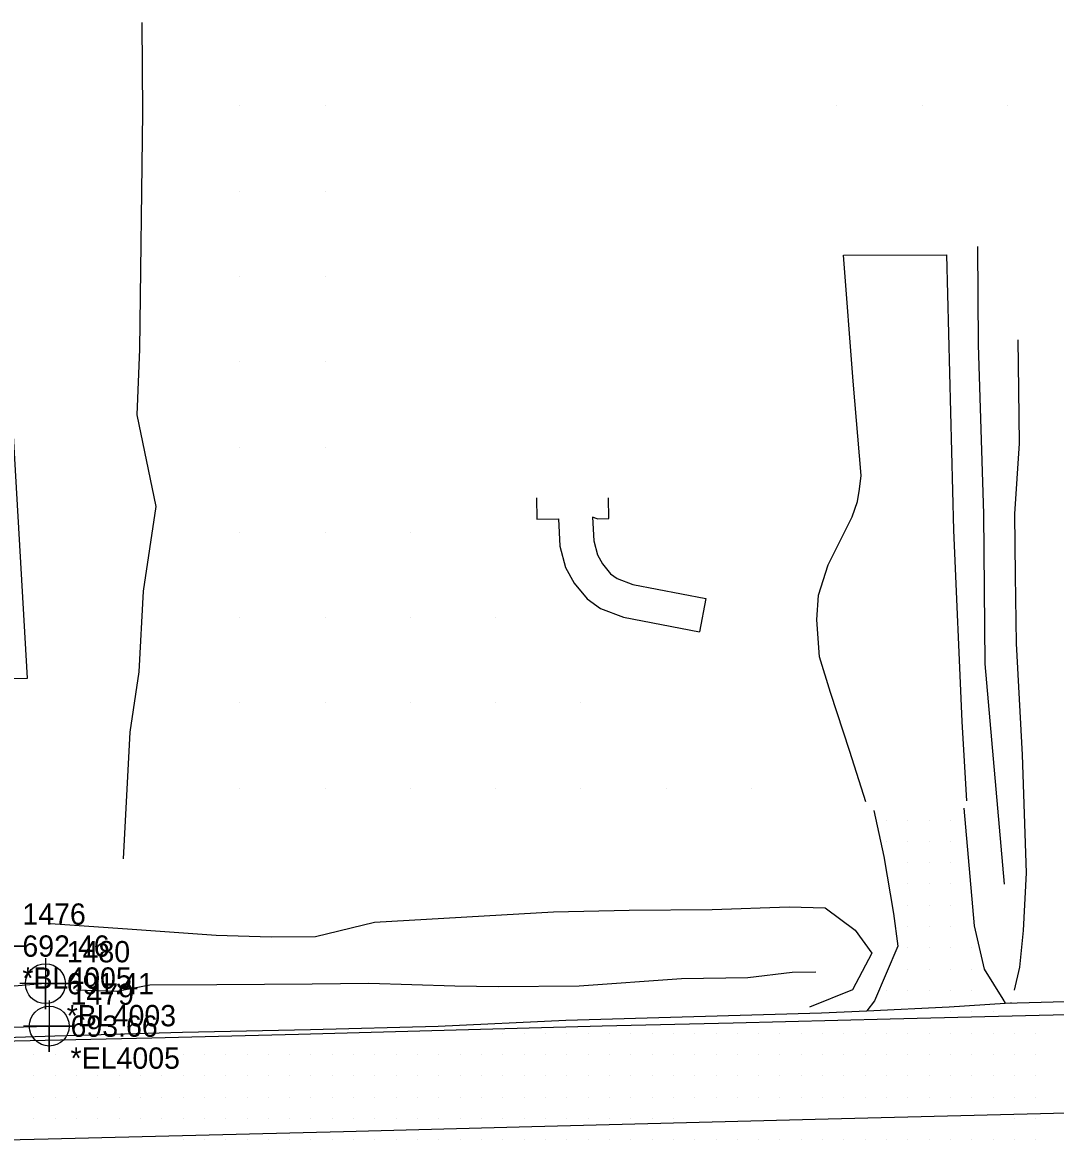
# Model space of a CAD drawing. Extents: x 1755643 to 1760494, y 736519 to 737621.
# Drawn here: x 1758089.9 to 1758211.1, y 736993.2 to 737124.8 of the extents above; entities that cross this region are included whole.
import ezdxf

# ---------------------------------------------------------------- set-up
doc = ezdxf.new("R2010")
doc.units = 0
for name, color, linetype in [('Exist Horizontal Alignment Direction Label', 7, 'Continuous'), ('Exist Railroads Standard Gauge', 7, 'Continuous'), ('Old_Level_1', 7, 'Continuous'), ('Old_Level_10', 7, 'Continuous'), ('Old_Level_2', 7, 'Continuous'), ('Old_Level_3', 7, 'Continuous'), ('Prop Corridor Linear Feature', 7, 'Continuous'), ('Prop Dimension', 7, 'Continuous'), ('Prop EOT Dash', 7, 'Continuous'), ('Prop Horizontal Alignment Direction Label', 7, 'Continuous'), ('Prop Lane Lines', 7, 'Continuous'), ('Prop Paint Stripe', 7, 'Continuous'), ('Scratch_Level_1', 7, 'Continuous'), ('Scratch_Level_2', 7, 'Continuous'), ('Scratch_Level_5', 7, 'Continuous'), ('Scratch_Level_6', 7, 'Continuous'), ('Scratch_Level_9', 7, 'Continuous')]:
    doc.layers.add(name, color=color, linetype=linetype)

msp = doc.modelspace()

# ---------------------------------------------------------------- linework, layer by layer
at = {"layer": 'Exist Railroads Standard Gauge'}
for p, q in [((1758157.31, 737066.59), (1758156.76, 737066.79)), ((1758170.05, 737057.25), (1758169.3, 737053.32))]:
    msp.add_line(p, q, dxfattribs=at)
for points in [[(1758103.92, 737124.79), (1758104, 737114.24), (1758103.64, 737086.47), (1758103.34, 737078.79), (1758105.56, 737068.02), (1758104.08, 737058.08), (1758103.56, 737048.62), (1758102.52, 737041.54), (1758101.73, 737026.7)], [(1758205.08, 737023.71), (1758202.81, 737049.55), (1758202.67, 737067.16), (1758202.04, 737086.99), (1758201.95, 737098.53)], [(1758188.82, 737033.39), (1758186.96, 737039.27), (1758184.66, 737046.19), (1758183.38, 737050.38), (1758183.08, 737054.72), (1758183.28, 737057.62), (1758184.41, 737061.19), (1758187.21, 737066.82), (1758187.83, 737068.59), (1758188.06, 737070.05), (1758188.29, 737071.64), (1758187.35, 737082.71), (1758186.21, 737097.48), (1758198.28, 737097.55), (1758199.09, 737065.26), (1758200.07, 737042.8), (1758200.61, 737033.5)], [(1758206.24, 737011.31), (1758206.89, 737013.98), (1758207.3, 737018.28), (1758207.67, 737025.04), (1758207.21, 737038.89), (1758206.48, 737051.96), (1758206.38, 737059.92), (1758206.31, 737067.16), (1758206.84, 737075.4), (1758206.78, 737081.71), (1758206.7, 737087.55)], [(1758061.63, 737030.06), (1758062.06, 737032.81), (1758064.05, 737038.81), (1758066.35, 737043.44), (1758068.93, 737046.42), (1758071.04, 737047.5), (1758090.51, 737047.87), (1758088.31, 737085.8)], [(1758150.21, 737069.02), (1758150.23, 737066.54), (1758152.76, 737066.56)], [(1758157.31, 737066.59), (1758158.67, 737066.6), (1758158.65, 737069.02)], [(1758152.76, 737066.56), (1758152.95, 737063.36), (1758153.6, 737060.86), (1758154.61, 737059.04), (1758156.13, 737057.2), (1758157.72, 737056.04), (1758160.39, 737055.03), (1758169.3, 737053.32)], [(1758156.76, 737066.79), (1758156.92, 737063.99), (1758157.35, 737062.36), (1758157.94, 737061.3), (1758158.89, 737060.13), (1758159.64, 737059.59), (1758161.48, 737058.89), (1758170.05, 737057.25)], [(1758093.18, 737019.13), (1758102.78, 737018.47), (1758112.61, 737017.75), (1758119.07, 737017.54), (1758124.28, 737017.58), (1758131.2, 737019.28), (1758152.21, 737020.47), (1758161.05, 737020.66), (1758170.8, 737020.74), (1758179.84, 737021.06), (1758184.07, 737020.96), (1758187.57, 737018.35), (1758189.52, 737015.64), (1758187.25, 737011.33), (1758182.21, 737009.29)], [(1758096.23, 737011.32), (1758100.97, 737011.19), (1758104.85, 737011.94), (1758112.72, 737011.97), (1758123.9, 737012.05), (1758130.53, 737012.1), (1758140.62, 737011.79), (1758145.72, 737011.71), (1758155.21, 737011.79), (1758167.21, 737012.66), (1758174.99, 737012.78), (1758180.19, 737013.39), (1758182.97, 737013.44)], [(1758205.87, 737009.83), (1758205.88, 737009.85)]]:
    msp.add_lwpolyline(points, dxfattribs=at)
at = {"layer": 'Old_Level_10'}
msp.add_lwpolyline([(1758092.6, 737015.06), (1758092.6, 737009.06), (1758092.6, 737012.06), (1758095.6, 737012.06), (1758089.6, 737012.06)], dxfattribs=at)
msp.add_circle((1758092.6, 737012.06), 2.34, dxfattribs=at)
at = {"layer": 'Prop Corridor Linear Feature'}
for points in [[(1758188.93, 737008.88), (1758198.61, 737009.34), (1758205.15, 737009.77)], [(1758205.15, 737009.77), (1758213.6, 737010), (1758228.6, 737009.79)]]:
    msp.add_lwpolyline(points, dxfattribs=at)
at = {"layer": 'Prop Dimension'}
msp.add_lwpolyline([(1758092.6, 737012.06), (1758073.32, 737010.44), (1758071.36, 737012.75)], dxfattribs=at)
at = {"layer": 'Prop Lane Lines'}
for points in [[(1758087.4, 737019.47), (1758087.4, 737013.47), (1758087.4, 737016.47), (1758090.4, 737016.47), (1758084.4, 737016.47)], [(1758093.05, 737010.08), (1758093.05, 737004.08), (1758093.05, 737007.08), (1758096.05, 737007.08), (1758090.05, 737007.08)]]:
    msp.add_lwpolyline(points, dxfattribs=at)
msp.add_circle((1758093.05, 737007.08), 2.34, dxfattribs=at)
at = {"layer": 'Prop Paint Stripe'}
for p, q in [((1758115.41, 737115), (1758115.41, 737115)), ((1758125.41, 737115), (1758125.41, 737115)), ((1758185.41, 737115), (1758185.41, 737115)), ((1758195.42, 737115), (1758195.42, 737115)), ((1758205.42, 737115), (1758205.42, 737115)), ((1758115.41, 737105), (1758115.41, 737105)), ((1758125.41, 737105), (1758125.41, 737105)), ((1758115.41, 737094.99), (1758115.41, 737094.99)), ((1758125.41, 737094.99), (1758125.41, 737094.99)), ((1758115.41, 737084.99), (1758115.41, 737084.99)), ((1758125.41, 737084.99), (1758125.41, 737084.99)), ((1758115.41, 737074.99), (1758115.41, 737074.99)), ((1758125.41, 737074.99), (1758125.41, 737074.99)), ((1758115.41, 737064.99), (1758115.41, 737064.99)), ((1758125.41, 737064.99), (1758125.41, 737064.99)), ((1758135.41, 737064.99), (1758135.41, 737064.99)), ((1758115.41, 737054.99), (1758115.41, 737054.99)), ((1758125.41, 737054.99), (1758125.41, 737054.99)), ((1758135.41, 737054.99), (1758135.41, 737054.99)), ((1758145.41, 737054.99), (1758145.41, 737054.99)), ((1758115.41, 737044.99), (1758115.41, 737044.99)), ((1758125.41, 737044.99), (1758125.41, 737044.99)), ((1758135.41, 737044.99), (1758135.41, 737044.99)), ((1758145.41, 737044.99), (1758145.41, 737044.99)), ((1758155.41, 737044.99), (1758155.41, 737044.99)), ((1758115.41, 737034.99), (1758115.41, 737034.99)), ((1758125.41, 737034.99), (1758125.41, 737034.99)), ((1758135.41, 737034.99), (1758135.41, 737034.99)), ((1758145.41, 737034.99), (1758145.41, 737034.99)), ((1758155.41, 737034.99), (1758155.41, 737034.99)), ((1758165.41, 737034.99), (1758165.41, 737034.99)), ((1758175.41, 737034.99), (1758175.41, 737034.99))]:
    msp.add_line(p, q, dxfattribs=at)
at = {"layer": 'Scratch_Level_1'}
msp.add_lwpolyline([(1758064.64, 737006.23), (1758067.75, 737005.95), (1758070.73, 737005.31), (1758078.73, 737005.43), (1758093.71, 737005.95), (1758108.69, 737006.38), (1758123.68, 737006.69), (1758138.67, 737007.07), (1758153.65, 737007.78), (1758168.64, 737008.2), (1758183.63, 737008.63), (1758188.93, 737008.88)], dxfattribs=at)
at = {"layer": 'Scratch_Level_2'}
for p, q in [((1758191.25, 737031.25), (1758191.25, 737031.25)), ((1758193.75, 737031.25), (1758193.75, 737031.25)), ((1758196.25, 737031.25), (1758196.25, 737031.25)), ((1758198.75, 737031.25), (1758198.75, 737031.25)), ((1758191.25, 737028.75), (1758191.25, 737028.75)), ((1758193.75, 737028.75), (1758193.75, 737028.75)), ((1758196.25, 737028.75), (1758196.25, 737028.75)), ((1758198.75, 737028.75), (1758198.75, 737028.75)), ((1758193.75, 737026.25), (1758193.75, 737026.25)), ((1758196.25, 737026.25), (1758196.25, 737026.25)), ((1758198.75, 737026.25), (1758198.75, 737026.25)), ((1758193.75, 737023.75), (1758193.75, 737023.75)), ((1758196.25, 737023.75), (1758196.25, 737023.75)), ((1758198.75, 737023.75), (1758198.75, 737023.75)), ((1758193.75, 737021.25), (1758193.75, 737021.25)), ((1758196.25, 737021.25), (1758196.25, 737021.25)), ((1758198.75, 737021.25), (1758198.75, 737021.25)), ((1758193.75, 737018.75), (1758193.75, 737018.75)), ((1758196.25, 737018.75), (1758196.25, 737018.75)), ((1758198.75, 737018.75), (1758198.75, 737018.75)), ((1758193.75, 737016.25), (1758193.75, 737016.25)), ((1758196.25, 737016.25), (1758196.25, 737016.25)), ((1758198.75, 737016.25), (1758198.75, 737016.25)), ((1758201.25, 737016.25), (1758201.25, 737016.25)), ((1758193.75, 737013.75), (1758193.75, 737013.75)), ((1758196.25, 737013.75), (1758196.25, 737013.75)), ((1758198.75, 737013.75), (1758198.75, 737013.75)), ((1758201.25, 737013.75), (1758201.25, 737013.75)), ((1758191.25, 737011.25), (1758191.25, 737011.25)), ((1758193.75, 737011.25), (1758193.75, 737011.25)), ((1758196.25, 737011.25), (1758196.25, 737011.25)), ((1758198.75, 737011.25), (1758198.75, 737011.25)), ((1758201.25, 737011.25), (1758201.25, 737011.25)), ((1758198.75, 737008.75), (1758198.75, 737008.75)), ((1758201.25, 737008.75), (1758201.25, 737008.75)), ((1758203.75, 737008.75), (1758203.75, 737008.75)), ((1758146.25, 737006.25), (1758146.25, 737006.25)), ((1758148.75, 737006.25), (1758148.75, 737006.25)), ((1758151.25, 737006.25), (1758151.25, 737006.25)), ((1758153.75, 737006.25), (1758153.75, 737006.25)), ((1758156.25, 737006.25), (1758156.25, 737006.25)), ((1758158.75, 737006.25), (1758158.75, 737006.25)), ((1758161.25, 737006.25), (1758161.25, 737006.25)), ((1758163.75, 737006.25), (1758163.75, 737006.25)), ((1758166.25, 737006.25), (1758166.25, 737006.25)), ((1758168.75, 737006.25), (1758168.75, 737006.25)), ((1758171.25, 737006.25), (1758171.25, 737006.25)), ((1758173.75, 737006.25), (1758173.75, 737006.25)), ((1758176.25, 737006.25), (1758176.25, 737006.25)), ((1758178.75, 737006.25), (1758178.75, 737006.25)), ((1758181.25, 737006.25), (1758181.25, 737006.25)), ((1758183.75, 737006.25), (1758183.75, 737006.25)), ((1758186.25, 737006.25), (1758186.25, 737006.25)), ((1758188.75, 737006.25), (1758188.75, 737006.25)), ((1758191.25, 737006.25), (1758191.25, 737006.25)), ((1758193.75, 737006.25), (1758193.75, 737006.25)), ((1758196.25, 737006.25), (1758196.25, 737006.25)), ((1758198.75, 737006.25), (1758198.75, 737006.25)), ((1758201.25, 737006.25), (1758201.25, 737006.25)), ((1758203.75, 737006.25), (1758203.75, 737006.25)), ((1758206.25, 737006.25), (1758206.25, 737006.25)), ((1758208.75, 737006.25), (1758208.75, 737006.25)), ((1758091.25, 737003.75), (1758091.25, 737003.75)), ((1758093.75, 737003.75), (1758093.75, 737003.75)), ((1758096.25, 737003.75), (1758096.25, 737003.75)), ((1758098.75, 737003.75), (1758098.75, 737003.75)), ((1758101.25, 737003.75), (1758101.25, 737003.75)), ((1758103.75, 737003.75), (1758103.75, 737003.75)), ((1758106.25, 737003.75), (1758106.25, 737003.75)), ((1758108.75, 737003.75), (1758108.75, 737003.75)), ((1758111.25, 737003.75), (1758111.25, 737003.75)), ((1758113.75, 737003.75), (1758113.75, 737003.75)), ((1758116.25, 737003.75), (1758116.25, 737003.75)), ((1758118.75, 737003.75), (1758118.75, 737003.75)), ((1758121.25, 737003.75), (1758121.25, 737003.75)), ((1758123.75, 737003.75), (1758123.75, 737003.75)), ((1758126.25, 737003.75), (1758126.25, 737003.75)), ((1758128.75, 737003.75), (1758128.75, 737003.75)), ((1758131.25, 737003.75), (1758131.25, 737003.75)), ((1758133.75, 737003.75), (1758133.75, 737003.75)), ((1758136.25, 737003.75), (1758136.25, 737003.75)), ((1758138.75, 737003.75), (1758138.75, 737003.75)), ((1758141.25, 737003.75), (1758141.25, 737003.75)), ((1758143.75, 737003.75), (1758143.75, 737003.75)), ((1758146.25, 737003.75), (1758146.25, 737003.75)), ((1758148.75, 737003.75), (1758148.75, 737003.75)), ((1758151.25, 737003.75), (1758151.25, 737003.75)), ((1758153.75, 737003.75), (1758153.75, 737003.75)), ((1758156.25, 737003.75), (1758156.25, 737003.75)), ((1758158.75, 737003.75), (1758158.75, 737003.75)), ((1758161.25, 737003.75), (1758161.25, 737003.75)), ((1758163.75, 737003.75), (1758163.75, 737003.75)), ((1758166.25, 737003.75), (1758166.25, 737003.75)), ((1758168.75, 737003.75), (1758168.75, 737003.75)), ((1758171.25, 737003.75), (1758171.25, 737003.75)), ((1758173.75, 737003.75), (1758173.75, 737003.75)), ((1758176.25, 737003.75), (1758176.25, 737003.75)), ((1758178.75, 737003.75), (1758178.75, 737003.75)), ((1758181.25, 737003.75), (1758181.25, 737003.75)), ((1758183.75, 737003.75), (1758183.75, 737003.75)), ((1758186.25, 737003.75), (1758186.25, 737003.75)), ((1758188.75, 737003.75), (1758188.75, 737003.75)), ((1758191.25, 737003.75), (1758191.25, 737003.75)), ((1758193.75, 737003.75), (1758193.75, 737003.75)), ((1758196.25, 737003.75), (1758196.25, 737003.75)), ((1758198.75, 737003.75), (1758198.75, 737003.75)), ((1758201.25, 737003.75), (1758201.25, 737003.75)), ((1758203.75, 737003.75), (1758203.75, 737003.75)), ((1758206.25, 737003.75), (1758206.25, 737003.75)), ((1758208.75, 737003.75), (1758208.75, 737003.75)), ((1758091.25, 737001.25), (1758091.25, 737001.25)), ((1758093.75, 737001.25), (1758093.75, 737001.25)), ((1758096.25, 737001.25), (1758096.25, 737001.25)), ((1758098.75, 737001.25), (1758098.75, 737001.25)), ((1758101.25, 737001.25), (1758101.25, 737001.25)), ((1758103.75, 737001.25), (1758103.75, 737001.25)), ((1758106.25, 737001.25), (1758106.25, 737001.25)), ((1758108.75, 737001.25), (1758108.75, 737001.25)), ((1758111.25, 737001.25), (1758111.25, 737001.25)), ((1758113.75, 737001.25), (1758113.75, 737001.25)), ((1758116.25, 737001.25), (1758116.25, 737001.25)), ((1758118.75, 737001.25), (1758118.75, 737001.25)), ((1758121.25, 737001.25), (1758121.25, 737001.25)), ((1758123.75, 737001.25), (1758123.75, 737001.25)), ((1758126.25, 737001.25), (1758126.25, 737001.25)), ((1758128.75, 737001.25), (1758128.75, 737001.25)), ((1758131.25, 737001.25), (1758131.25, 737001.25)), ((1758133.75, 737001.25), (1758133.75, 737001.25)), ((1758136.25, 737001.25), (1758136.25, 737001.25)), ((1758138.75, 737001.25), (1758138.75, 737001.25)), ((1758141.25, 737001.25), (1758141.25, 737001.25)), ((1758143.75, 737001.25), (1758143.75, 737001.25)), ((1758146.25, 737001.25), (1758146.25, 737001.25)), ((1758148.75, 737001.25), (1758148.75, 737001.25)), ((1758151.25, 737001.25), (1758151.25, 737001.25)), ((1758153.75, 737001.25), (1758153.75, 737001.25)), ((1758156.25, 737001.25), (1758156.25, 737001.25)), ((1758158.75, 737001.25), (1758158.75, 737001.25)), ((1758161.25, 737001.25), (1758161.25, 737001.25)), ((1758163.75, 737001.25), (1758163.75, 737001.25)), ((1758166.25, 737001.25), (1758166.25, 737001.25)), ((1758168.75, 737001.25), (1758168.75, 737001.25)), ((1758171.25, 737001.25), (1758171.25, 737001.25)), ((1758173.75, 737001.25), (1758173.75, 737001.25)), ((1758176.25, 737001.25), (1758176.25, 737001.25)), ((1758178.75, 737001.25), (1758178.75, 737001.25)), ((1758181.25, 737001.25), (1758181.25, 737001.25)), ((1758183.75, 737001.25), (1758183.75, 737001.25)), ((1758186.25, 737001.25), (1758186.25, 737001.25)), ((1758188.75, 737001.25), (1758188.75, 737001.25)), ((1758191.25, 737001.25), (1758191.25, 737001.25)), ((1758193.75, 737001.25), (1758193.75, 737001.25)), ((1758196.25, 737001.25), (1758196.25, 737001.25)), ((1758198.75, 737001.25), (1758198.75, 737001.25)), ((1758201.25, 737001.25), (1758201.25, 737001.25)), ((1758203.75, 737001.25), (1758203.75, 737001.25)), ((1758206.25, 737001.25), (1758206.25, 737001.25)), ((1758208.75, 737001.25), (1758208.75, 737001.25)), ((1758091.25, 736998.75), (1758091.25, 736998.75)), ((1758093.75, 736998.75), (1758093.75, 736998.75)), ((1758096.25, 736998.75), (1758096.25, 736998.75)), ((1758098.75, 736998.75), (1758098.75, 736998.75)), ((1758101.25, 736998.75), (1758101.25, 736998.75)), ((1758103.75, 736998.75), (1758103.75, 736998.75)), ((1758106.25, 736998.75), (1758106.25, 736998.75)), ((1758108.75, 736998.75), (1758108.75, 736998.75)), ((1758111.25, 736998.75), (1758111.25, 736998.75)), ((1758113.75, 736998.75), (1758113.75, 736998.75)), ((1758116.25, 736998.75), (1758116.25, 736998.75)), ((1758118.75, 736998.75), (1758118.75, 736998.75)), ((1758121.25, 736998.75), (1758121.25, 736998.75)), ((1758123.75, 736998.75), (1758123.75, 736998.75)), ((1758126.25, 736998.75), (1758126.25, 736998.75)), ((1758128.75, 736998.75), (1758128.75, 736998.75)), ((1758131.25, 736998.75), (1758131.25, 736998.75)), ((1758133.75, 736998.75), (1758133.75, 736998.75)), ((1758136.25, 736998.75), (1758136.25, 736998.75)), ((1758138.75, 736998.75), (1758138.75, 736998.75)), ((1758141.25, 736998.75), (1758141.25, 736998.75)), ((1758143.75, 736998.75), (1758143.75, 736998.75)), ((1758146.25, 736998.75), (1758146.25, 736998.75)), ((1758148.75, 736998.75), (1758148.75, 736998.75)), ((1758151.25, 736998.75), (1758151.25, 736998.75)), ((1758153.75, 736998.75), (1758153.75, 736998.75)), ((1758156.25, 736998.75), (1758156.25, 736998.75)), ((1758158.75, 736998.75), (1758158.75, 736998.75)), ((1758161.25, 736998.75), (1758161.25, 736998.75)), ((1758163.75, 736998.75), (1758163.75, 736998.75)), ((1758166.25, 736998.75), (1758166.25, 736998.75)), ((1758168.75, 736998.75), (1758168.75, 736998.75)), ((1758171.25, 736998.75), (1758171.25, 736998.75)), ((1758173.75, 736998.75), (1758173.75, 736998.75)), ((1758176.25, 736998.75), (1758176.25, 736998.75)), ((1758178.75, 736998.75), (1758178.75, 736998.75)), ((1758181.25, 736998.75), (1758181.25, 736998.75)), ((1758183.75, 736998.75), (1758183.75, 736998.75)), ((1758186.25, 736998.75), (1758186.25, 736998.75)), ((1758188.75, 736998.75), (1758188.75, 736998.75)), ((1758191.25, 736998.75), (1758191.25, 736998.75)), ((1758193.75, 736998.75), (1758193.75, 736998.75)), ((1758196.25, 736998.75), (1758196.25, 736998.75)), ((1758198.75, 736998.75), (1758198.75, 736998.75)), ((1758201.25, 736998.75), (1758201.25, 736998.75)), ((1758203.75, 736998.75), (1758203.75, 736998.75)), ((1758206.25, 736998.75), (1758206.25, 736998.75)), ((1758208.75, 736998.75), (1758208.75, 736998.75)), ((1758091.25, 736996.25), (1758091.25, 736996.25)), ((1758093.75, 736996.25), (1758093.75, 736996.25)), ((1758096.25, 736996.25), (1758096.25, 736996.25)), ((1758098.75, 736996.25), (1758098.75, 736996.25)), ((1758101.25, 736996.25), (1758101.25, 736996.25)), ((1758103.75, 736996.25), (1758103.75, 736996.25)), ((1758106.25, 736996.25), (1758106.25, 736996.25)), ((1758108.75, 736996.25), (1758108.75, 736996.25)), ((1758111.25, 736996.25), (1758111.25, 736996.25)), ((1758113.75, 736996.25), (1758113.75, 736996.25)), ((1758116.25, 736996.25), (1758116.25, 736996.25)), ((1758118.75, 736996.25), (1758118.75, 736996.25)), ((1758121.25, 736996.25), (1758121.25, 736996.25)), ((1758123.75, 736996.25), (1758123.75, 736996.25)), ((1758126.25, 736996.25), (1758126.25, 736996.25)), ((1758128.75, 736996.25), (1758128.75, 736996.25)), ((1758131.25, 736996.25), (1758131.25, 736996.25)), ((1758133.75, 736996.25), (1758133.75, 736996.25)), ((1758136.25, 736996.25), (1758136.25, 736996.25)), ((1758138.75, 736996.25), (1758138.75, 736996.25)), ((1758141.25, 736996.25), (1758141.25, 736996.25)), ((1758143.75, 736996.25), (1758143.75, 736996.25)), ((1758146.25, 736996.25), (1758146.25, 736996.25)), ((1758148.75, 736996.25), (1758148.75, 736996.25)), ((1758151.25, 736996.25), (1758151.25, 736996.25)), ((1758153.75, 736996.25), (1758153.75, 736996.25)), ((1758156.25, 736996.25), (1758156.25, 736996.25)), ((1758158.75, 736996.25), (1758158.75, 736996.25)), ((1758161.25, 736996.25), (1758161.25, 736996.25)), ((1758163.75, 736996.25), (1758163.75, 736996.25)), ((1758166.25, 736996.25), (1758166.25, 736996.25)), ((1758206.25, 736996.25), (1758206.25, 736996.25)), ((1758208.75, 736996.25), (1758208.75, 736996.25)), ((1758108.75, 736993.75), (1758108.75, 736993.75)), ((1758111.25, 736993.75), (1758111.25, 736993.75)), ((1758113.75, 736993.75), (1758113.75, 736993.75)), ((1758116.25, 736993.75), (1758116.25, 736993.75)), ((1758118.75, 736993.75), (1758118.75, 736993.75)), ((1758121.25, 736993.75), (1758121.25, 736993.75)), ((1758123.75, 736993.75), (1758123.75, 736993.75)), ((1758126.25, 736993.75), (1758126.25, 736993.75)), ((1758128.75, 736993.75), (1758128.75, 736993.75)), ((1758131.25, 736993.75), (1758131.25, 736993.75)), ((1758133.75, 736993.75), (1758133.75, 736993.75)), ((1758136.25, 736993.75), (1758136.25, 736993.75)), ((1758138.75, 736993.75), (1758138.75, 736993.75)), ((1758141.25, 736993.75), (1758141.25, 736993.75)), ((1758143.75, 736993.75), (1758143.75, 736993.75)), ((1758146.25, 736993.75), (1758146.25, 736993.75)), ((1758148.75, 736993.75), (1758148.75, 736993.75)), ((1758151.25, 736993.75), (1758151.25, 736993.75)), ((1758153.75, 736993.75), (1758153.75, 736993.75)), ((1758156.25, 736993.75), (1758156.25, 736993.75)), ((1758158.75, 736993.75), (1758158.75, 736993.75)), ((1758161.25, 736993.75), (1758161.25, 736993.75)), ((1758163.75, 736993.75), (1758163.75, 736993.75)), ((1758166.25, 736993.75), (1758166.25, 736993.75)), ((1758168.75, 736993.75), (1758168.75, 736993.75)), ((1758171.25, 736993.75), (1758171.25, 736993.75)), ((1758173.75, 736993.75), (1758173.75, 736993.75)), ((1758176.25, 736993.75), (1758176.25, 736993.75)), ((1758178.75, 736993.75), (1758178.75, 736993.75)), ((1758181.25, 736993.75), (1758181.25, 736993.75)), ((1758183.75, 736993.75), (1758183.75, 736993.75)), ((1758186.25, 736993.75), (1758186.25, 736993.75)), ((1758188.75, 736993.75), (1758188.75, 736993.75)), ((1758191.25, 736993.75), (1758191.25, 736993.75)), ((1758193.75, 736993.75), (1758193.75, 736993.75)), ((1758196.25, 736993.75), (1758196.25, 736993.75)), ((1758198.75, 736993.75), (1758198.75, 736993.75)), ((1758201.25, 736993.75), (1758201.25, 736993.75)), ((1758203.75, 736993.75), (1758203.75, 736993.75)), ((1758206.25, 736993.75), (1758206.25, 736993.75)), ((1758208.75, 736993.75), (1758208.75, 736993.75))]:
    msp.add_line(p, q, dxfattribs=at)
at = {"layer": 'Scratch_Level_5'}
for points in [[(1758064.69, 737004.75), (1758072.66, 737005.01), (1758089, 737005.36), (1758105.09, 737005.72), (1758122.29, 737006.14), (1758136.53, 737006.53), (1758157.9, 737007.11), (1758173.26, 737007.48), (1758191.67, 737007.95), (1758209.14, 737008.37), (1758232.19, 737008.9), (1758248.18, 737009.28), (1758264.32, 737009.73)], [(1758064.8, 736993.19), (1758092.92, 736993.85), (1758127.56, 736994.73), (1758149.64, 736995.32), (1758184.39, 736996.19), (1758213.94, 736996.95), (1758233.95, 736997.45), (1758251.62, 736997.88), (1758264.67, 736998.25)]]:
    msp.add_lwpolyline(points, dxfattribs=at)
at = {"layer": 'Scratch_Level_6'}
for points in [[(1758189.76, 737032.36), (1758190.92, 737026.99), (1758192.06, 737020.27), (1758192.58, 737016.46), (1758189.85, 737010.04), (1758188.93, 737008.88)], [(1758200.3, 737032.64), (1758201.54, 737018.83), (1758202.69, 737013.77), (1758204.89, 737010.23), (1758205.15, 737009.77)]]:
    msp.add_lwpolyline(points, dxfattribs=at)
at = {"layer": 'Scratch_Level_9'}
msp.add_lwpolyline([(1758087.4, 737016.47), (1758068.85, 737015.99), (1758070.44, 737006.47), (1758093.05, 737007.08)], dxfattribs=at)

# ---------------------------------------------------------------- texts
at = {"layer": 'Exist Horizontal Alignment Direction Label'}
for s, p in [('*BL4005', (1758089.9, 737011.47)), ('*EL4005', (1758095.55, 737002.08))]:
    msp.add_text(s, height=2.5, dxfattribs=at).set_placement(p)
at = {"layer": 'Old_Level_1'}
msp.add_text('1480', height=2.5, dxfattribs=at).set_placement((1758095.1, 737014.56))
at = {"layer": 'Old_Level_2'}
msp.add_text('691.41', height=2.5, dxfattribs=at).set_placement((1758095.1, 737010.81))
at = {"layer": 'Old_Level_3'}
for s, p in [('692.46', (1758089.9, 737015.22)), ('693.66', (1758095.55, 737005.83))]:
    msp.add_text(s, height=2.5, dxfattribs=at).set_placement(p)
at = {"layer": 'Prop EOT Dash'}
for s, p in [('1476', (1758089.9, 737018.97)), ('1479', (1758095.55, 737009.58))]:
    msp.add_text(s, height=2.5, dxfattribs=at).set_placement(p)
at = {"layer": 'Prop Horizontal Alignment Direction Label'}
msp.add_text('*BL4003', height=2.5, dxfattribs=at).set_placement((1758095.1, 737007.06))

doc.saveas('drawing.dxf')
